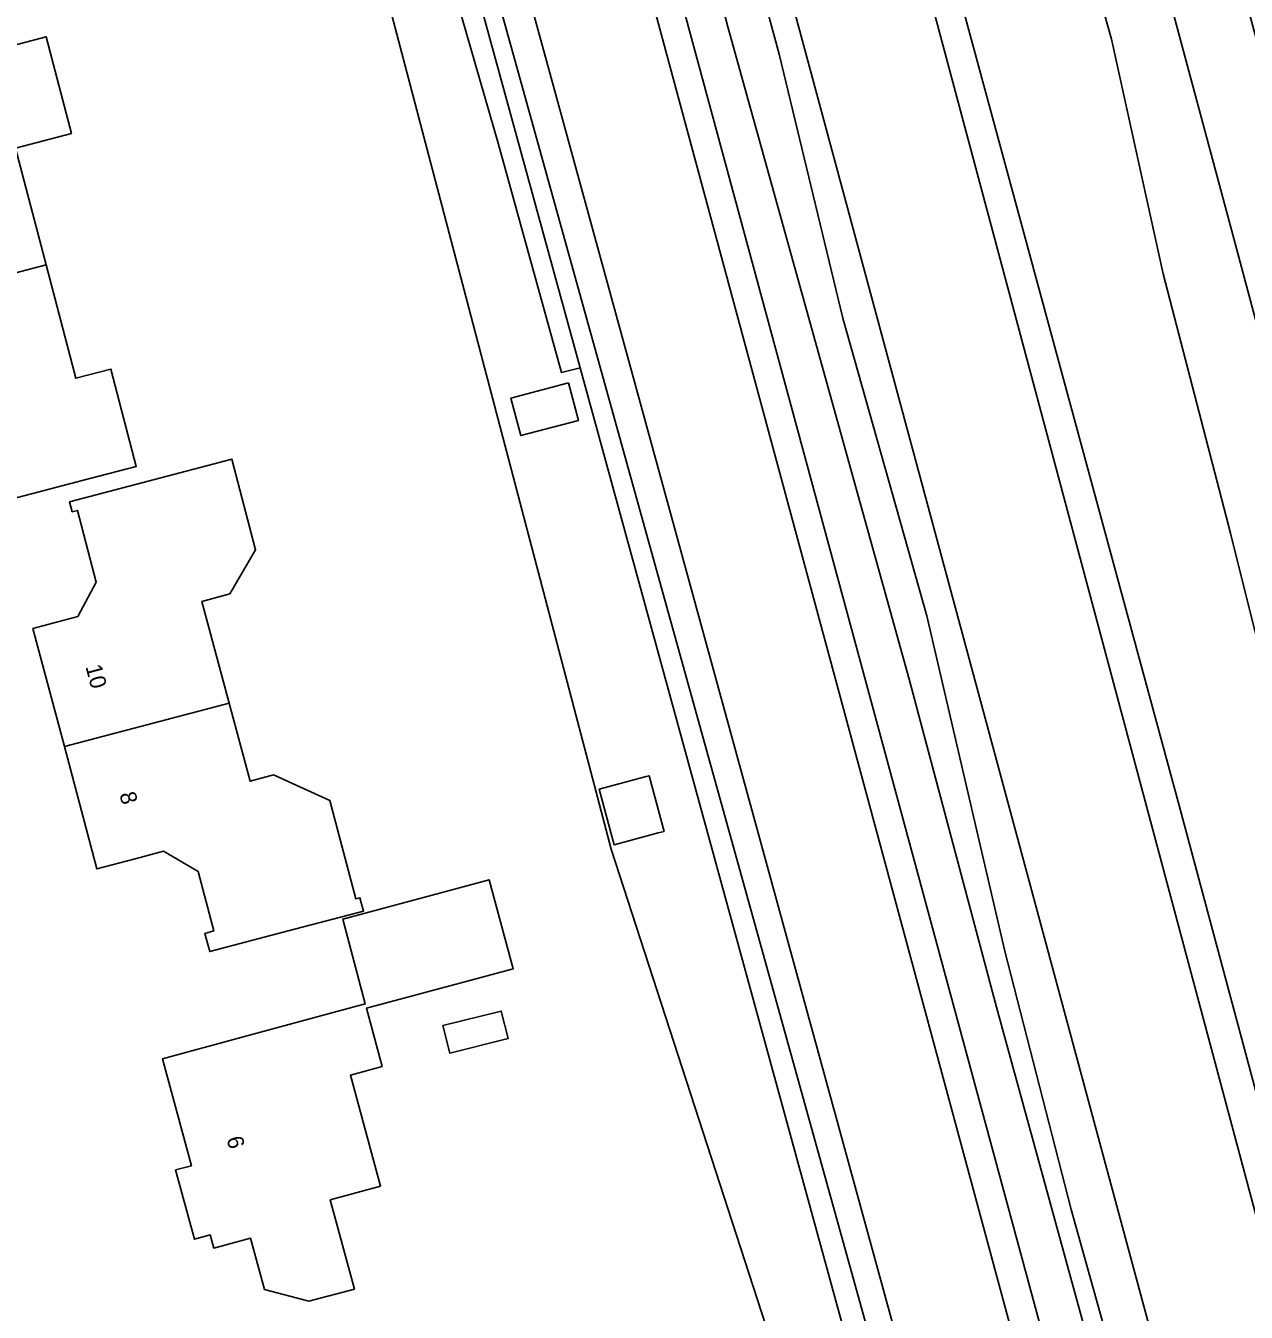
# Model space of a CAD drawing. Extents: x 162156 to 163172, y 378995 to 380779.
# Drawn here: x 162732.1 to 162807.3, y 380254.5 to 380333.8 of the extents above; entities that cross this region are included whole.
import ezdxf

# ---------------------------------------------------------------- set-up
doc = ezdxf.new("R2010")
doc.units = 0
for name, color, linetype in [('IMGEO_Berm_groen', 7, 'Continuous'), ('IMGEO_Erf', 7, 'Continuous'), ('IMGEO_Fietspad_gesloten', 7, 'Continuous'), ('IMGEO_Gemengd_bos', 7, 'Continuous'), ('IMGEO_Groenvoorziening', 7, 'Continuous'), ('IMGEO_Hek', 7, 'Continuous'), ('IMGEO_Pand', 7, 'Continuous'), ('IMGEO_Pand_nummerreeks', 7, 'Continuous'), ('IMGEO_Rijbaan_lokaal_onverhard', 7, 'Continuous'), ('IMGEO_Rijbaan_regionaal_gesloten', 7, 'Continuous')]:
    doc.layers.add(name, color=color, linetype=linetype)

msp = doc.modelspace()

# ---------------------------------------------------------------- linework, layer by layer
at = {"layer": 'IMGEO_Berm_groen'}
for points in [[(162794.766, 380347.98), (162799.001, 380332.962), (162802.183, 380318.487), (162806.333, 380302.503), (162810.152, 380287.192), (162815.784, 380268.272), (162819.72, 380252.917), (162824.398, 380233.353), (162827.76, 380214.252), (162828.219, 380211.645), (162831.862, 380198.178), (162836.227, 380181.255), (162840.443, 380167.498), (162844.58, 380151.283), (162852.467, 380130.786), (162854.365, 380123.049), (162864.701, 380086.482), (162869.2, 380069.897), (162880.273, 380030.302), (162885.795, 380009.884), (162894.022, 379977.905), (162894.819, 379974.807), (162899.22, 379955.866)], [(162842.433, 380176.601), (162835.452, 380202.413), (162832.557, 380215.85), (162832.33, 380216.922), (162831.773, 380220.437), (162830.505, 380228.44), (162829.432, 380235.217), (162829.034, 380236.7), (162825.25, 380250.824), (162819.579, 380271.987), (162813.552, 380294.481), (162806.616, 380320.369), (162800.793, 380342.098)]]:
    msp.add_lwpolyline(points, dxfattribs=at)
at = {"layer": 'IMGEO_Erf'}
msp.add_lwpolyline([(162783.125, 380251.148), (162766.255, 380312.701), (162765.118, 380312.403), (162761.207, 380326.545), (162746.139, 380378.78)], dxfattribs=at)
for points in [[(162733.347, 380333.107), (162734.91, 380327.133), (162731.47, 380326.234), (162733.349, 380319.051), (162735.18, 380312.052), (162737.343, 380312.618), (162738.911, 380306.621), (162736.052, 380305.873), (162731.203, 380304.604), (162729.788, 380310.01), (162725.173, 380308.803), (162723.191, 380316.379), (162721.147, 380324.192), (162725.749, 380325.396), (162724.348, 380330.753), (162729.186, 380332.019)], [(162765.546, 380311.769), (162766.154, 380309.459), (162762.598, 380308.523), (162761.99, 380310.833)], [(162739.634, 380305.705), (162744.8, 380307.064), (162746.265, 380301.49), (162744.673, 380298.768), (162742.949, 380298.306), (162744.632, 380292.027), (162745.92, 380287.221), (162747.357, 380287.606), (162750.841, 380286.024), (162752.434, 380279.973), (162752.692, 380280.043), (162752.914, 380279.221), (162748.27, 380277.996), (162743.435, 380276.72), (162743.133, 380277.841), (162743.683, 380277.989), (162742.718, 380281.652), (162740.579, 380282.902), (162739.383, 380282.583), (162738.841, 380282.439), (162736.484, 380281.811), (162734.476, 380289.353), (162732.538, 380296.632), (162735.313, 380297.371), (162736.442, 380299.496), (162735.28, 380303.914), (162734.96, 380303.829), (162734.798, 380304.433)], [(162770.336, 380287.51), (162770.51, 380287.557), (162771.432, 380284.13), (162771.078, 380284.035), (162768.351, 380283.301), (162767.429, 380286.727)], [(162753.015, 380273.493), (162751.632, 380278.721), (162758.527, 380280.577), (162760.66, 380281.151), (162762.136, 380275.665), (162760.004, 380275.091), (162753.087, 380273.229), (162754.061, 380269.628), (162752.109, 380269.1), (162753.958, 380262.263), (162750.858, 380261.424), (162752.346, 380255.924), (162749.542, 380255.166), (162746.814, 380255.89), (162745.957, 380259.057), (162743.689, 380258.443), (162743.469, 380259.256), (162742.489, 380258.991), (162741.334, 380263.26), (162742.307, 380263.523), (162740.524, 380270.113), (162745.351, 380271.419)], [(162757.807, 380272.162), (162761.4, 380273.055), (162761.821, 380271.359), (162758.229, 380270.466)]]:
    msp.add_lwpolyline(points, close=True, dxfattribs=at)
at = {"layer": 'IMGEO_Fietspad_gesloten'}
msp.add_lwpolyline([(162734.133, 380481.792), (162732.921, 380486.487), (162731.275, 380485.433), (162731.822, 380483.297), (162732.486, 380480.708), (162737.147, 380462.444), (162744.041, 380435.433), (162753.469, 380399.171), (162793.043, 380252.594), (162793.743, 380250), (162802.348, 380218.82), (162802.932, 380216.599), (162805.251, 380208.274), (162805.604, 380206.953), (162807.15, 380207.372), (162795.604, 380250), (162794.831, 380252.855), (162755.082, 380399.61), (162738.941, 380462.93)], close=True, dxfattribs=at)
at = {"layer": 'IMGEO_Gemengd_bos'}
for points in [[(162725.222, 380467.154), (162726.017, 380463.29), (162732.512, 380440.284), (162732.513, 380440.281), (162737.886, 380421.251), (162740.789, 380409.911), (162740.791, 380409.902), (162744.134, 380396.843), (162784.538, 380251.354), (162784.914, 380250), (162794.037, 380217.15), (162795.456, 380217.538), (162786.56, 380250), (162786.126, 380251.585), (162745.395, 380400.219)], [(162727.791, 380464.262), (162728.963, 380460.227), (162739.025, 380425.583), (162745.395, 380400.219), (162786.126, 380251.585), (162786.56, 380250), (162795.456, 380217.538), (162794.037, 380217.15), (162792.555, 380216.745), (162791.089, 380216.345), (162783.48, 380243.983), (162782.999, 380245.41), (162771.731, 380247.855), (162748.489, 380207.589), (162718.287, 380199.505), (162706.233, 380218.452), (162704.484, 380215.83), (162716.066, 380197.828)], [(162718.821, 380196.787), (162791.243, 380215.891), (162802.348, 380218.82), (162793.743, 380250), (162793.043, 380252.594), (162753.469, 380399.171)]]:
    msp.add_lwpolyline(points, dxfattribs=at)
for points in [[(162744.134, 380396.843), (162740.791, 380409.902), (162740.789, 380409.911), (162737.886, 380421.251), (162732.513, 380440.281), (162732.512, 380440.284), (162731.457, 380440.006), (162737.08, 380420.274), (162739.846, 380409.655), (162742.744, 380398.533), (162743.009, 380397.514), (162766.255, 380312.701), (162783.125, 380251.148), (162783.44, 380250), (162784.806, 380245.018), (162792.555, 380216.745), (162794.037, 380217.15), (162784.914, 380250), (162784.538, 380251.354)], [(162739.846, 380409.655), (162737.785, 380409.114), (162741.065, 380398.164), (162741.083, 380398.095), (162746.139, 380378.78), (162761.207, 380326.545), (162765.118, 380312.403), (162766.255, 380312.701), (162743.009, 380397.514), (162742.744, 380398.533)]]:
    msp.add_lwpolyline(points, close=True, dxfattribs=at)
at = {"layer": 'IMGEO_Groenvoorziening'}
for points in [[(162797.432, 380253.232), (162791.916, 380273.301), (162786.532, 380293.517), (162775.358, 380333.719), (162765.415, 380371.737), (162759.745, 380391.983), (162736.16, 380483.349), (162735.346, 380483.727), (162734.512, 380483.576)], [(162734.133, 380481.792), (162738.941, 380462.93), (162755.082, 380399.61), (162794.831, 380252.855), (162795.604, 380250), (162807.15, 380207.372), (162834.019, 380108.166), (162847.388, 380056.989), (162849.58, 380050.068), (162853.046, 380036.529), (162855.696, 380027.529), (162859.063, 380014.988), (162859.82, 380012.908), (162860.297, 380010.248), (162863.326, 380000), (162875.925, 379953.557)], [(162813.854, 380226.666), (162817.23, 380227.352), (162816.464, 380231.836), (162815.904, 380231.68), (162809.099, 380256.047), (162784.998, 380346.141), (162773.546, 380387.659), (162773.943, 380387.473), (162777.214, 380394.954), (162776.751, 380395.208)], [(162824.398, 380233.353), (162819.72, 380252.917), (162815.784, 380268.272), (162810.152, 380287.192), (162806.333, 380302.503), (162802.183, 380318.487), (162799.001, 380332.962), (162794.766, 380347.98), (162789.801, 380363.383), (162782.448, 380390.827), (162779.724, 380393.579), (162778.946, 380394.005), (162774.375, 380387.232), (162775.963, 380386.075), (162803.167, 380285.715), (162810.981, 380256.603), (162817.461, 380232.08), (162816.975, 380231.952), (162818.407, 380227.871), (162820.972, 380228.529)], [(162766.299, 380383.503), (162801.292, 380253.797), (162806.635, 380233.468), (162807.467, 380230.468)], [(162812.966, 380210.526), (162807.467, 380230.468), (162806.635, 380233.468), (162801.292, 380253.797), (162766.299, 380383.503)], [(162771.243, 380358.925), (162778.519, 380332.031), (162782.456, 380315.752), (162787.624, 380297.403), (162792.424, 380276.743), (162796.525, 380260.819), (162798.599, 380253.404), (162804.6, 380231.946), (162813.274, 380202.726), (162817.832, 380185.507), (162820.474, 380174.332), (162830.289, 380136.987), (162838.721, 380106.165), (162845.723, 380082.59), (162848.029, 380072.7), (162850.821, 380063.544), (162873.068, 379986.284), (162876.406, 379973.928), (162879.54, 379963.774)]]:
    msp.add_lwpolyline(points, dxfattribs=at)
msp.add_lwpolyline([(162775.963, 380386.075), (162774.375, 380387.232), (162773.943, 380387.473), (162773.546, 380387.659), (162784.998, 380346.141), (162809.099, 380256.047), (162815.904, 380231.68), (162816.464, 380231.836), (162816.975, 380231.952), (162817.461, 380232.08), (162810.981, 380256.603), (162803.167, 380285.715)], close=True, dxfattribs=at)
at = {"layer": 'IMGEO_Hek'}
msp.add_lwpolyline([(162778.738, 380250.508), (162768.177, 380283.038), (162722.067, 380458.358), (162720.737, 380463.414)], dxfattribs=at)
at = {"layer": 'IMGEO_Pand'}
for points in [[(162733.349, 380319.051), (162731.47, 380326.234), (162734.91, 380327.133), (162733.347, 380333.107), (162729.186, 380332.019), (162724.348, 380330.753), (162725.749, 380325.396), (162721.147, 380324.192), (162723.191, 380316.379)], [(162737.343, 380312.618), (162735.18, 380312.052), (162733.349, 380319.051), (162723.191, 380316.379), (162725.173, 380308.803), (162729.788, 380310.01), (162731.203, 380304.604), (162736.052, 380305.873), (162738.911, 380306.621)], [(162765.546, 380311.769), (162761.99, 380310.833), (162762.598, 380308.523), (162766.154, 380309.459)], [(162744.632, 380292.027), (162742.949, 380298.306), (162744.673, 380298.768), (162746.265, 380301.49), (162744.8, 380307.064), (162739.634, 380305.705), (162734.798, 380304.433), (162734.96, 380303.829), (162735.28, 380303.914), (162736.442, 380299.496), (162735.313, 380297.371), (162732.538, 380296.632), (162734.476, 380289.353)], [(162744.632, 380292.027), (162734.476, 380289.353), (162736.484, 380281.811), (162738.841, 380282.439), (162739.383, 380282.583), (162740.579, 380282.902), (162742.718, 380281.652), (162743.683, 380277.989), (162743.133, 380277.841), (162743.435, 380276.72), (162748.27, 380277.996), (162752.914, 380279.221), (162752.692, 380280.043), (162752.434, 380279.973), (162750.841, 380286.024), (162747.357, 380287.606), (162745.92, 380287.221)], [(162770.336, 380287.51), (162767.429, 380286.727), (162768.351, 380283.301), (162771.078, 380284.035), (162771.432, 380284.13), (162770.51, 380287.557)], [(162754.061, 380269.628), (162753.087, 380273.229), (162760.004, 380275.091), (162762.136, 380275.665), (162760.66, 380281.151), (162758.527, 380280.577), (162751.632, 380278.721), (162753.015, 380273.493), (162745.351, 380271.419), (162740.524, 380270.113), (162742.307, 380263.523), (162741.334, 380263.26), (162742.489, 380258.991), (162743.469, 380259.256), (162743.689, 380258.443), (162745.957, 380259.057), (162746.814, 380255.89), (162749.542, 380255.166), (162752.346, 380255.924), (162750.858, 380261.424), (162753.958, 380262.263), (162752.109, 380269.1)], [(162757.807, 380272.162), (162758.229, 380270.466), (162761.821, 380271.359), (162761.4, 380273.055)]]:
    msp.add_lwpolyline(points, close=True, dxfattribs=at)
at = {"layer": 'IMGEO_Rijbaan_lokaal_onverhard'}
for points in [[(162887.734, 379923.859), (162885.297, 379937.582), (162879.54, 379963.774), (162876.406, 379973.928), (162873.068, 379986.284), (162850.821, 380063.544), (162848.029, 380072.7), (162845.723, 380082.59), (162838.721, 380106.165), (162830.289, 380136.987), (162820.474, 380174.332), (162817.832, 380185.507), (162813.274, 380202.726), (162804.6, 380231.946), (162798.599, 380253.404), (162796.525, 380260.819), (162792.424, 380276.743), (162787.624, 380297.403), (162782.456, 380315.752), (162778.519, 380332.031), (162771.243, 380358.925), (162764.081, 380387.552), (162762.982, 380391.944), (162737.511, 380495.432)], [(162765.415, 380371.737), (162775.358, 380333.719), (162786.532, 380293.517), (162791.916, 380273.301), (162797.432, 380253.232), (162800.754, 380239.27), (162803.814, 380228.274), (162815.649, 380183.144), (162836.518, 380107.168), (162850.444, 380055.192), (162872.222, 379980.619), (162875.477, 379970.319), (162877.403, 379963.088)]]:
    msp.add_lwpolyline(points, dxfattribs=at)
at = {"layer": 'IMGEO_Rijbaan_regionaal_gesloten'}
msp.add_lwpolyline([(162800.793, 380342.098), (162806.616, 380320.369), (162813.552, 380294.481), (162819.579, 380271.987), (162825.25, 380250.824), (162829.034, 380236.7), (162833.19, 380237.778), (162827.681, 380257.645), (162815.722, 380304.13), (162776.289, 380450.017)], dxfattribs=at)

# ---------------------------------------------------------------- texts
at = {"layer": 'IMGEO_Pand_nummerreeks'}
for s, rotation, p in [('10', 284.9088, (162735.772, 380294.283)), ('8', 284.9088, (162737.863, 380286.426)), ('6', 285.13733, (162744.463, 380265.201))]:
    msp.add_text(s, height=1, rotation=rotation, dxfattribs=at).set_placement(p)

doc.saveas('drawing.dxf')
